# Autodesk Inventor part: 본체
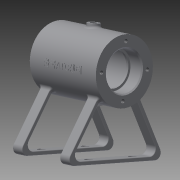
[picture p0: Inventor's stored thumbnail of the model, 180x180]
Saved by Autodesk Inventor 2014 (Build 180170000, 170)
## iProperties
Created: 2016-03
Part Number: 본체
Material: 일반
Document SubType Name: Modeling
Designer: 703-15
Density: 1 g/cm^3
Appearance: 기본값
Author: 703-15
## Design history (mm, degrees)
sketch "스케치1"
  geometry: L1 (-15.556, 65)-(15.556, 65); L2 (-35, 91)-(35, 91); L3 (35, 91)-(35, 81); L4 (35, 81)-(23, 81); L5 (23, 81)-(23, 79); L6 (23, 79)-(21.091, 79); L7 (21.091, 79)-(21.091, 83.206); L8 (21.091, 83.206)-(-20.909, 83.206); L9 (-20.909, 83.206)-(-20.909, 79); L10 (-20.909, 79)-(-23, 79); L11 (-23, 79)-(-23, 81); L12 (-23, 81)-(-35, 81); L13 (-35, 81)-(-35, 91); 3 further points
  constraints: 26 end point, 7 parallel, 4 perpendicular, 2 midpoint, 2 vertical alignment, 1 collinear, 1 horizontal
  dimensions: "d0" = 65 distance from line of point (0, 0) L1; "d1" = 70 distance of L2.start L2.end; "d2" = 52 diameter of L2 L1; "d3" = 32 diameter of L4 L1; "d4" = 28 diameter of L6 L1; "d5" = 28 diameter of L10 L1; "d6" = 32 diameter of L12 L1; "d7" = 12 distance of L3.end L4.end; "d8" = 42 distance of L7.end L8.end; "d9" = 12 distance of L11.end L12.end
revolve "회전1" sketch "스케치1" stored, may be unused: angle "d10" = 90 deg
node "작업 평면2"
  node "작업 평면1"
sketch "스케치2"
  geometry: L1 (-18.235, 18.534)-(-65, 45.534); L2 (-65, 45.534)-(-65, -45.534); L3 (-65, -45.534)-(-18.235, -18.534); L4 (0, 0)-(-67.936, 0); L5 (-20.291, 16.257)-(-62, 40.338); L6 (-62, 40.338)-(-62, -40.338); L7 (-62, -40.338)-(-20.291, -16.257); A1 r 26 centre (0, 0) between (-18.235, 18.534) and (-18.235, -18.534) reference; 2 further points
  constraints: 14 end point, 4 point on circle, 2 coincident, 1 midpoint, 1 perpendicular, 1 vertical, 2 other
  dimensions: "d12" = 30 deg angle of L4 L3; "d13" = 30 deg angle of L4 L1; "d14" = 3 distance between parallel lines of L1 L5
extrude "돌출1" join sketch "스케치2" distance "d15" = 10; taper "d16" = 0 deg
fillet "모깎기1" dims "d17" = 5
sketch "스케치3"
  geometry: L1 (0, -5.196)-(10, -5.196) reference; L2 (0, -5.196)-(0, 68.551) reference; L3 (10, 68.551)-(0, 68.551) reference; L4 (10, -5.196)-(10, 68.551) reference; 3 further points
  dimensions: "d18" = 20 vertical distance of point (5, 11.677) point (-20, 31.677); "d19" = 40 distance of point (5, 51.677) point (5, 11.677)
hole "구멍1" sketch "스케치3" at (5, 11.677), (5, 51.677) diameter "d20" = 6; stored, may be unused: countersink angle "d24" = 90 deg, drill point angle "d26" = 118 deg; dims "d21" = 6, "d22" = 4, "d23" = 2, "d25" = 8
node "작업 평면4"
  node "작업 평면3"
sketch "스케치4"
  geometry: C1 r 5 at (0, 0); 1 further point
  constraints: 1 centre point, 1 coincident
  dimensions: "d28" = 10 diameter of C1
extrude "돌출2" join sketch "스케치4" distance "d29" = 5; taper "d30" = 0 deg
sketch "스케치5"
  geometry: C1 r 5 at (0, 0) reference; 1 further point
  constraints: 1 coincident
hole "구멍2" sketch "스케치5" at (0, 0) diameter "d31" = 5.188; stored, may be unused: countersink angle "d35" = 90 deg, drill point angle "d37" = 0 deg; dims "d32" = 20, "d33" = 4, "d34" = 2, "d36" = 20
sketch "스케치6"
  geometry: C1 r 2.594 at (0, 0) reference; C2 r 5 at (0, 0) reference; C3 r 6 at (0, 0); 1 further point
  constraints: 1 centre point, 1 coincident
  dimensions: "d41" = 12 diameter of C3
extrude "돌출3" join sketch "스케치6" distance "d42" = 5; taper "d43" = 0 deg
sketch "스케치7"
  geometry: C1 r 26 at (0, 0) reference; 2 further points
  constraints: 1 vertical alignment
  dimensions: "d44" = 21 distance of C1.centre point (0, 21)
hole "구멍3" sketch "스케치7" at (0, 21) diameter "d45" = 3.242; stored, may be unused: countersink angle "d49" = 90 deg, drill point angle "d51" = 118 deg; dims "d46" = 8, "d47" = 4, "d48" = 2, "d50" = 10
node "작업 평면6"
sketch "스케치8"
  geometry: L1 (35, 26)-(-35, 26) reference; L2 (-35, 26)-(-35, -26) reference; 2 further points
  constraints: 1 other
  dimensions: "d55" = 35 distance from line of L2 point (0, 0); "d56" = 26 distance from line of L1 point (0, 0)
feature "엠보싱1" sketch "스케치8" dims "d57" = 0.5, "d58" = 0
chamfer "모따기1" distance "d59" = 1; stored, may be unused: second distance "d60" = 2, angle "d61" = 45 deg
fillet "모깎기2" dims "d62" = 3
fillet "모깎기3" dims "d63" = 0.3
fillet "모깎기4" dims "d64" = 0.5
fillet "모깎기5" dims "d65" = 0.5
fillet "모깎기6" dims "d66" = 2
fillet "모깎기7" dims "d67" = 3
node "솔리드1"
mirror "대칭1"
pattern_circular "원형 패턴1" dims angle "d39" = 165 deg
pattern_circular "원형 패턴2" dims angle "d53" = 360 deg
mirror "대칭2"
node "투영된 루프1"
node "작업 평면5"
other parameters: "d27" = 3
